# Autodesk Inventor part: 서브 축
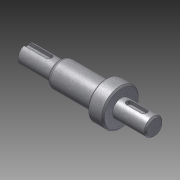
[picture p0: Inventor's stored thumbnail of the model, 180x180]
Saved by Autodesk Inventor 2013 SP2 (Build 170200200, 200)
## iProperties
Created: 2016-04
Part Number: 서브 축
Document SubType Name: Modeling
Designer: mdu
Density: 1 g/cm^3
Mass: 19.9624 g
Surface Area: 57.7178 cm^2
Volume: 19.9624 cm^3
Material: 강철, 연강
Author: mdu
Revision Number: 1
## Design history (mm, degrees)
sketch "스케치1"
  geometry: L1 (-16.331, 0)-(-103.831, 0); L2 (-16.331, 0)-(-16.331, -6); L3 (-16.331, -6)-(-38.831, -6); L4 (-38.831, -12.5)-(-46.5, -12.5); L5 (-46.5, -8.5)-(-79.013, -8.5); L6 (-103.831, -6)-(-103.831, 0); L7 (-46.5, -8.5)-(-46.5, -12.5); L8 (-38.831, -6)-(-38.831, -12.5); L9 (-46.5, 12.249)-(-46.5, -12.249) reference; L10 (-38.831, -17)-(-38.831, 17) reference; L11 (-103.831, -6)-(-80.831, -6); L12 (-80.831, -6)-(-80.831, -7.45); L13 (-80.831, -7.45)-(-79.013, -8.5); 2 further points
  constraints: 23 end point, 6 perpendicular, 2 collinear, 2 parallel, 1 horizontal, 1 midpoint, 1 point on line
  dimensions: "d1" = 12 diameter of L3 L1; "d2" = 25 diameter of L4 L1; "d3" = 17 diameter of L5 L1; "d18" = 22.5 distance of L2.end L3.end; "d20" = 65 distance between parallel lines of L6 L8; "d21" = 7.66872 distance of L4.start L4.end (derived); "d28" = 12 diameter of L11 L1; "d29" = 23 distance of L6.start L11.end; "d30" = 14.9 diameter of L12.end L1; "d32" = 30 deg angle of L5 L13
revolve "회전1" sketch "스케치1" stored, may be unused: angle "d5" = 90 deg
chamfer "모따기1" distance "d6" = 1; stored, may be unused: second distance "d7" = 2, angle "d8" = 45 deg
node "작업 평면1"
sketch "스케치2"
  geometry: L1 (11.25, 5)-(11.25, -5) reference; L2 (-5.75, -2)-(4.25, -2); L3 (4.25, 2)-(-5.75, 2); A1 r 2 centre (4.25, 0) between (4.25, -2) and (4.25, 2); A2 r 2 centre (-5.75, 0) between (-5.75, 2) and (-5.75, -2); 2 further points
  constraints: 4 end point, 4 point on circle, 4 tangent, 2 centre point, 1 horizontal alignment, 1 midpoint, 1 parallel, 1 perpendicular
  dimensions: "d9" = 4 distance between parallel lines of L2 L3; "d10" = 14 dimension on A1 A2; "d11" = 5 distance edge to line of A1 L1
extrude "돌출1" cut sketch "스케치2" distance "d12" = 2.5; taper "d13" = 0 deg
node "작업 평면2"
sketch "스케치3"
  geometry: L1 (-103.831, -5)-(-103.831, 5) reference; L2 (-103.831, 2)-(-87.831, 2); L3 (-87.831, -2)-(-103.831, -2); A1 r 2 centre (-87.831, 0) between (-87.831, -2) and (-87.831, 2); 2 further points
  constraints: 4 end point, 2 perpendicular, 2 point on circle, 2 point on line, 2 tangent, 1 centre point, 1 horizontal alignment, 1 midpoint
  dimensions: "d14" = 4 distance between parallel lines of L3 L2; "d15" = 18 dimension on A1 L1
extrude "돌출2" cut sketch "스케치3" distance "d16" = 2.5; taper "d17" = 0 deg
sketch "스케치4"
  geometry: C1 r 12.5 at (0, 0) reference; 1 further point
extrude "돌출3" join sketch "스케치4" distance "d22" = 3; taper "d23" = 0 deg
chamfer "모따기2" distance "d24" = 1; stored, may be unused: second distance "d25" = 2, angle "d26" = 45 deg
fillet "모깎기1" dims "d34" = 1
fillet "모깎기2" dims "d35" = 2
node "솔리드1"
node "참조4"
node "참조5"
other parameters: "d33" = 6
